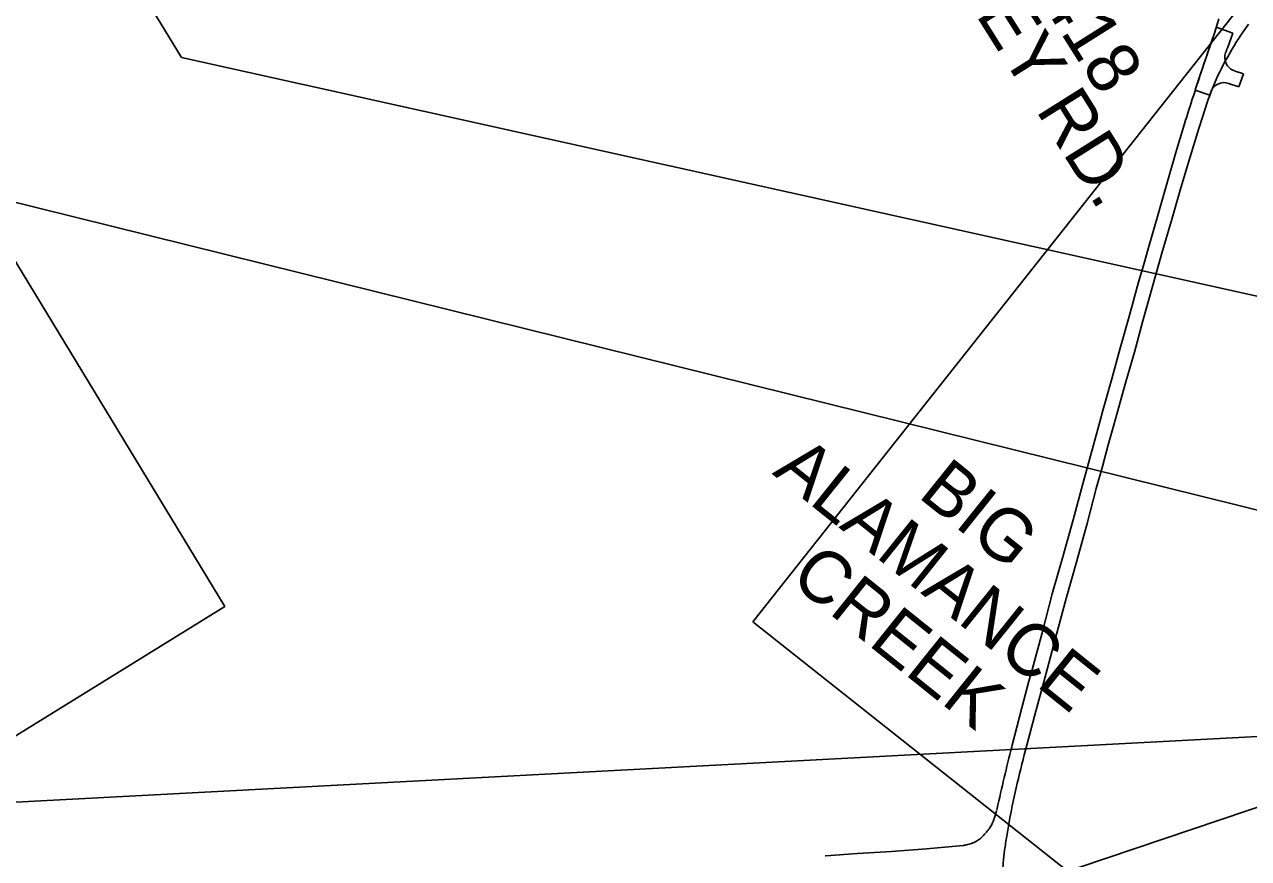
# Model space of a CAD drawing. Extents: x 1750583 to 1791140, y 783580 to 827376.
# Drawn here: x 1779520 to 1781276, y 812926 to 814121 of the extents above; entities that cross this region are included whole.
import ezdxf

# ---------------------------------------------------------------- set-up
doc = ezdxf.new("R2010")
doc.units = 0
for name, color, linetype in [('COGO Default Parcel', 7, 'Continuous'), ('Exist CMT EOP', 7, 'Continuous'), ('Prop Dimension Text', 7, 'Continuous'), ('Prop EOT', 7, 'Continuous'), ('Prop Shade Heavy', 7, 'Continuous'), ('Sheet Clip Boundary CELL', 7, 'Continuous'), ('Sheet Plan Layout CELL', 7, 'Continuous')]:
    doc.layers.add(name, color=color, linetype=linetype)

msp = doc.modelspace()

# ---------------------------------------------------------------- linework, layer by layer
at = {"layer": 'COGO Default Parcel'}
for p, q in [((1779745.8, 814074.3), (1779070.7, 815175.4)), ((1781963.9, 813582), (1779745.8, 814074.3)), ((1781749.3, 813311.1), (1779484.8, 813871.7)), ((1781595.3, 813116.5), (1779475.1, 813004.6)), ((1781579.6, 813096.7), (1779460.8, 812384.2))]:
    msp.add_line(p, q, dxfattribs=at)
at = {"layer": 'Exist CMT EOP'}
for p, q in [((1781264.9, 814106.2), (1781276.1, 814122)), ((1780914.8, 812994.6), (1780914.4, 812993.4)), ((1780915.2, 812995.4), (1780915.5, 812997)), ((1780715.2, 812932.7), (1780669.7, 812929.3)), ((1780669.7, 812929.3), (1780668.8, 812929.2))]:
    msp.add_line(p, q, dxfattribs=at)
for points in [[(1780936.5, 813085.9), (1780950.8, 813141.5), (1780961.2, 813179.6), (1780966.1, 813197.9), (1780979.9, 813249.1), (1780994.6, 813304.9), (1781009.5, 813358.1), (1781024.4, 813411.3), (1781038.5, 813462.6), (1781062.8, 813551.9), (1781067.3, 813567.7), (1781080.1, 813613.3), (1781092.2, 813657.3), (1781104.8, 813702.5), (1781118.5, 813751.7), (1781126.2, 813779.1), (1781132, 813799.5), (1781145.5, 813845.9), (1781158.8, 813893), (1781171.7, 813937.8), (1781184.2, 813979.1)], [(1780956.2, 813081), (1780970.9, 813136.6), (1780985.6, 813191.5), (1780999.7, 813243.3), (1781014.6, 813298.5), (1781029.6, 813352.4), (1781044.5, 813405.7), (1781057.7, 813456.2), (1781066.4, 813487.8), (1781074.8, 813518.5), (1781082.2, 813545.3), (1781087.1, 813562.9), (1781100.3, 813608.9), (1781112.3, 813651.8), (1781124.6, 813696.7), (1781138.2, 813745.7), (1781151.9, 813793.7), (1781165.4, 813840.5), (1781179, 813887.4), (1781192.6, 813931.8), (1781204.9, 813972.1)], [(1780866.7, 812944), (1780814.2, 812939.4), (1780763.9, 812935.5), (1780715.2, 812932.7)]]:
    msp.add_lwpolyline(points, dxfattribs=at)
msp.add_ellipse((1783377.8, 812427.3), major_axis=(276.8, 2644.5), ratio=0.949816, start_param=1.419476, end_param=1.453842, dxfattribs=at)
for points in [[(1781123.7, 814794.6), (1781151.9, 814749.7), (1781175.4, 814711.9), (1781204, 814667.2), (1781230.1, 814626.4), (1781255.5, 814585.1), (1781282.9, 814541.4), (1781309, 814500.8), (1781338.1, 814453.8), (1781362.4, 814415.7), (1781389.1, 814373.2), (1781417.2, 814328.4), (1781443.8, 814286), (1781469.2, 814245.3), (1781496.3, 814201.9), (1781523.3, 814159.3), (1781551.5, 814114.9), (1781575, 814076.8), (1781602.3, 814034.5), (1781628.7, 813992.4), (1781657.7, 813946.4), (1781683, 813906.2), (1781710.5, 813862.1), (1781734.7, 813823.6), (1781763.1, 813779.2), (1781788.4, 813738.4), (1781814.8, 813696.3), (1781842.4, 813653.4), (1781868.9, 813610.7), (1781895.8, 813568.7), (1781924.4, 813523.6), (1781950.6, 813481.8), (1781976.7, 813442.7), (1782004.4, 813401.4), (1782032, 813360.1), (1782060.8, 813317.5), (1782089.2, 813276.6), (1782119.2, 813233.3), (1782146.2, 813195.7), (1782175.1, 813155.1), (1782204.1, 813115.4), (1782233.2, 813075.7), (1782263.8, 813034.4), (1782294, 812994.3), (1782325, 812953.9), (1782354.4, 812916.2), (1782385, 812877.4), (1782417.2, 812837.3), (1782449.4, 812797.6), (1782479.5, 812761.8), (1782513.2, 812720.7), (1782543, 812685), (1782576.4, 812645.9), (1782608.5, 812608.7), (1782640.7, 812571.4), (1782677.4, 812531), (1782710.3, 812494.7), (1782741.2, 812460.8), (1782775.5, 812424.1), (1782810.1, 812387), (1782844.4, 812350.7), (1782880.7, 812313.2), (1782914.8, 812277.6), (1782949.9, 812242.2), (1782985.1, 812206.9), (1783022.4, 812170.4), (1783054.9, 812138.6), (1783094.7, 812100.5), (1783130, 812066.9), (1783162.7, 812036.2), (1783200.8, 812001.5), (1783239.6, 811966), (1783275.5, 811933.3), (1783312.5, 811900.8)], [(1781184.2, 813979.1), (1781197, 814019.1), (1781204.5, 814042.1), (1781215.7, 814075.6), (1781221.5, 814092.3), (1781229.6, 814116.8), (1781233.3, 814129.5)], [(1781204.9, 813972.1), (1781220.4, 814019.7), (1781240.4, 814064.7), (1781264.9, 814106.2)], [(1780923.2, 812753.2), (1780921.4, 812808.1), (1780921.5, 812864.1), (1780926.3, 812937.4), (1780929.2, 812957.5), (1780942.8, 813026.9), (1780956.2, 813081)], [(1780914.4, 812993.4), (1780910.9, 812981.5), (1780905.7, 812970.7), (1780902.4, 812966), (1780897.6, 812960.3), (1780891.5, 812954.4), (1780885.8, 812950.5), (1780878.8, 812947.2), (1780871.2, 812944.9), (1780866.7, 812944)]]:
    msp.add_spline(points, degree=3, dxfattribs=at)
at = {"layer": 'Prop EOT'}
for p, q in [((1781229.8, 814117.4), (1781253.4, 814108.9)), ((1781253.4, 814108.9), (1781245.7, 814087.3)), ((1781219.6, 814087.2), (1781222.3, 814094.6)), ((1781217.1, 814079.7), (1781217, 814079.4)), ((1781255.5, 814055.2), (1781268.7, 814050.6)), ((1781262.1, 814031.9), (1781247.4, 814037)), ((1781262.1, 814031.9), (1781268.7, 814050.6)), ((1781220.5, 814019.9), (1781199.6, 814027.1)), ((1781220.5, 814019.9), (1781221.9, 814024.3))]:
    msp.add_line(p, q, dxfattribs=at)
for centre, radius, start, end in [((1781262.1, 814074.1), 20, 160.325, 250.5767), ((1785549, 812541.3), 4572.7, 160.2381, 160.325), ((1781240.9, 814018.1), 20, 70.8267, 161.9951)]:
    msp.add_arc(centre, radius, start, end, dxfattribs=at)
msp.add_open_spline([(1781199.6, 814027.1), (1781201.2, 814032.1), (1781202.8, 814037.1), (1781204.5, 814042.1), (1781208.1, 814053.3), (1781211.9, 814064.5), (1781215.7, 814075.6), (1781217.6, 814081.2), (1781219.5, 814086.7), (1781221.5, 814092.3), (1781224.2, 814100.4), (1781227.2, 814108.5), (1781229.6, 814116.8), (1781229.7, 814117), (1781229.7, 814117.2), (1781229.8, 814117.4)], degree=3, dxfattribs=at)
at = {"layer": 'Prop Shade Heavy'}
for p, q in [((1781253.4, 814108.9), (1781229.8, 814117.4)), ((1781245.7, 814087.3), (1781253.4, 814108.9)), ((1781222.3, 814094.6), (1781221.7, 814093.1)), ((1781268.7, 814050.6), (1781255.5, 814055.2)), ((1781247.4, 814037), (1781262.1, 814031.9)), ((1781262.1, 814031.9), (1781268.7, 814050.6)), ((1781199.6, 814027.1), (1781220.5, 814019.9)), ((1781220.5, 814019.9), (1781221.9, 814024.3))]:
    msp.add_line(p, q, dxfattribs=at)
for points in [[(1781222.3, 814094.7), (1781222.3, 814094.6)], [(1781217.4, 814080.7), (1781217.1, 814079.7), (1781217, 814079.4), (1781212, 814064.8)], [(1781212, 814064.8), (1781212, 814064.8)]]:
    msp.add_lwpolyline(points, dxfattribs=at)
for centre, radius, start, end in [((1781262.1, 814074.1), 20, 160.325, 250.5767), ((1785549, 812541.3), 4572.7, 160.2381, 160.325), ((1781240.9, 814018.1), 20, 70.8267, 161.9951)]:
    msp.add_arc(centre, radius, start, end, dxfattribs=at)
for points in [[(1781229.8, 814117.4), (1781229.7, 814117.2), (1781229.7, 814117), (1781229.6, 814116.8), (1781227.5, 814109.3), (1781224.8, 814102), (1781222.3, 814094.7)], [(1781221.7, 814093.1), (1781221.6, 814092.8), (1781221.5, 814092.6), (1781221.5, 814092.3), (1781220.1, 814088.4), (1781218.8, 814084.6), (1781217.4, 814080.7)], [(1781212, 814064.8), (1781209.5, 814057.2), (1781206.9, 814049.7), (1781204.5, 814042.1), (1781202.8, 814037.1), (1781201.2, 814032.1), (1781199.6, 814027.1)]]:
    msp.add_open_spline(points, degree=3, dxfattribs=at)
at = {"layer": 'Sheet Clip Boundary CELL'}
msp.add_lwpolyline([(1778136.8, 816039.3), (1779807.6, 813286.9), (1778788.4, 812657.1), (1781190.7, 808756.5), (1783067.6, 810931.3), (1785138.2, 813464), (1782097.7, 818459.4)], close=True, dxfattribs=at)
at = {"layer": 'Sheet Plan Layout CELL'}
msp.add_lwpolyline([(1780565.2, 813264.9), (1781623.5, 814601.6), (1784200, 812561.7), (1783141.7, 811225.1)], close=True, dxfattribs=at)

# ---------------------------------------------------------------- texts
at = {"layer": 'Prop Dimension Text'}
for s, rotation, p in [('NEELLEY RD.', 302.1612, (1780714.9, 814404.6)), ('SR 3418', 302.2047, (1780856.9, 814346.4)), ('ALAMANCE', 321.2639, (1780591.8, 813477.4)), ('BIG ', 321.2639, (1780800.3, 813444.8)), ('CREEK', 321.2639, (1780616, 813323.4))]:
    msp.add_text(s, height=75, rotation=rotation, dxfattribs=at).set_placement(p)

doc.saveas('drawing.dxf')
